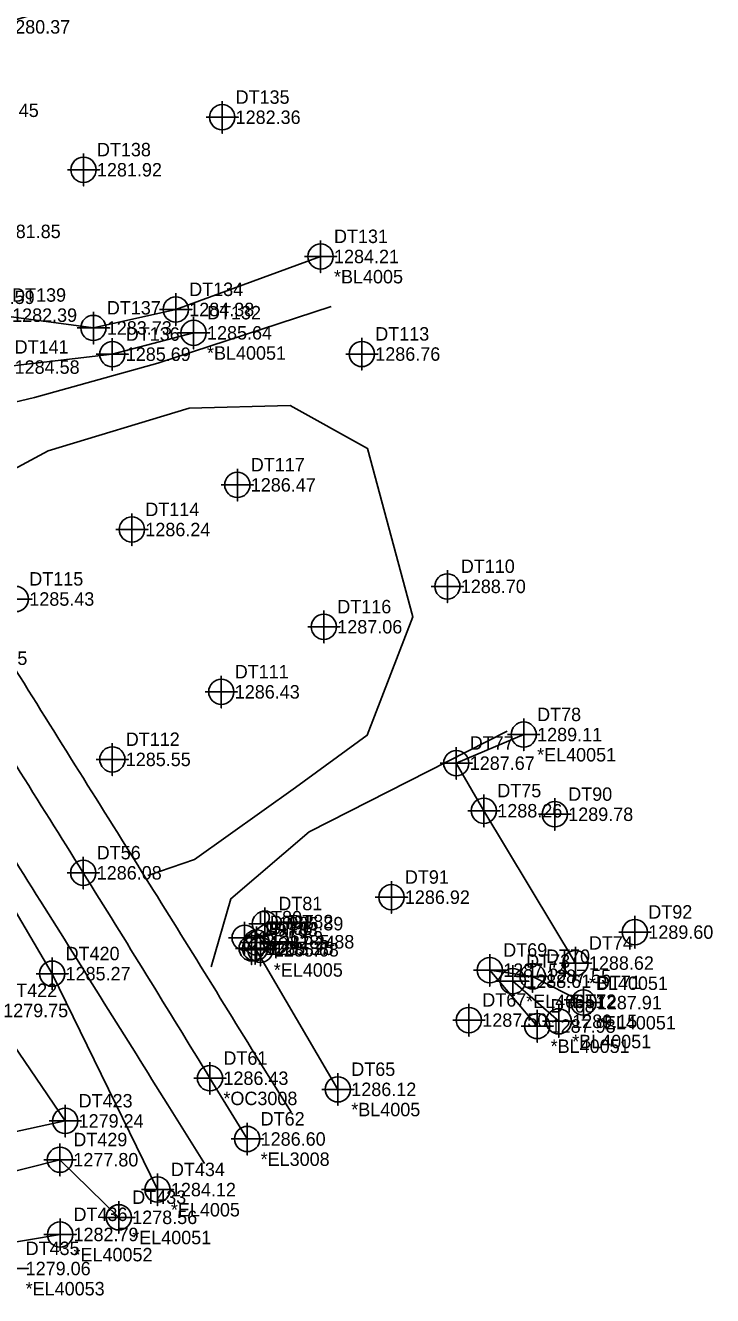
# Model space of a CAD drawing. Extents: x 1394009 to 1394411, y 957864 to 958364.
# Drawn here: x 1394283.7 to 1394411.5, y 957878.6 to 958114.8 of the extents above; entities that cross this region are included whole.
import ezdxf

# ---------------------------------------------------------------- set-up
doc = ezdxf.new("R2010")
doc.units = 0
for name, color, linetype in [('Exist DTM Breakline', 7, 'Continuous'), ('Exist DTM Breakline Cogo Comment', 7, 'Continuous'), ('Exist DTM Breakline Cogo Elevation', 7, 'Continuous'), ('Exist DTM Breakline Cogo Number', 7, 'Continuous'), ('Exist DTM Breakline Cogo Point CELL', 7, 'Continuous'), ('Exist DTM Crownline', 7, 'Continuous'), ('Exist DTM Regular Point Cogo Elevation', 7, 'Continuous'), ('Exist Roads EOP', 7, 'Continuous'), ('Exist Roads Soil', 7, 'Continuous'), ('Exist Structure Minor Culvert Topo', 7, 'Continuous'), ('Exist Structure Minor Culvert Topo Terminator', 7, 'Continuous'), ('Exist Structure Minor Footbridge', 7, 'Continuous'), ('Exist Structure Minor Footbridge Terminator', 7, 'Continuous'), ('PH Exist DTM NCFMP LIDAR Elevation Point', 7, 'Continuous'), ('Raster_Level_0', 7, 'Continuous')]:
    doc.layers.add(name, color=color, linetype=linetype)

msp = doc.modelspace()

# ---------------------------------------------------------------- linework, layer by layer
at = {"layer": 'Exist DTM Breakline'}
for p, q in [((1394382.8635, 957929.5842), (1394374.3045, 957937.0396)), ((1394254.6438, 957883.9212), (1394290.1223, 957889.9518))]:
    msp.add_line(p, q, dxfattribs=at)
for points in [[(1394338.5703, 958071.7873), (1394311.6428, 958061.939), (1394296.3165, 958058.5038), (1394278.7037, 958060.8799), (1394270.8162, 958064.205), (1394260.0757, 958069.6149), (1394248.6938, 958087.5642), (1394243.8244, 958095.3933), (1394260.8199, 958104.7758), (1394277.4189, 958114.4853), (1394301.9851, 958121.8746)], [(1394234.7161, 958087.1493), (1394208.4745, 958071.86), (1394207.051, 958069.7897), (1394210.8783, 958071.9618), (1394213.0858, 958066.3393), (1394211.818, 958067.823), (1394208.5647, 958061.9703), (1394223.9737, 958040.8216), (1394237.157, 958012.3346), (1394253.5006, 957985.8224), (1394267.2603, 957974.749), (1394288.6525, 957938.4432), (1394308.2436, 957898.2998)], [(1394314.9529, 958057.597), (1394299.8393, 958053.6184), (1394279.177, 958051.2301), (1394266.5791, 958043.3997), (1394258.6023, 958048.4386), (1394249.7488, 958062.8318), (1394236.4026, 958078.4617), (1394232.5982, 958084.3218)], [(1394202.6193, 958029.3354), (1394215.0019, 958016.2345), (1394221.6713, 958003.4334), (1394237.1401, 957997.6779), (1394243.3584, 957984.1351), (1394256.2425, 957964.9576), (1394277.0443, 957931.6004), (1394291.0752, 957911.067), (1394259.429, 957904.1903), (1394243.1444, 957902.5266)], [(1394385.9719, 957940.4138), (1394368.9383, 957968.739), (1394363.8098, 957977.5834), (1394376.341, 957982.8965)], [(1394341.7843, 957916.9337), (1394326.395, 957943.1604), (1394325.7531, 957943.1461), (1394324.4454, 957945.1081), (1394328.2194, 957947.7402), (1394330.2585, 957944.3788), (1394327.3729, 957942.881)], [(1394378.8606, 957928.706), (1394370.0349, 957939.0949), (1394378.0113, 957937.9487), (1394387.4448, 957933.0667)], [(1394243.646, 957897.9549), (1394263.7341, 957897.1943), (1394290.0967, 957903.851), (1394301.0447, 957893.1375)]]:
    msp.add_lwpolyline(points, dxfattribs=at)
at = {"layer": 'Exist DTM Breakline Cogo Point CELL'}
for points in [[(1394338.5703, 958074.7873), (1394338.5703, 958068.7873), (1394338.5703, 958071.7873), (1394341.5703, 958071.7873), (1394335.5703, 958071.7873)], [(1394311.6428, 958064.939), (1394311.6428, 958058.939), (1394311.6428, 958061.939), (1394314.6428, 958061.939), (1394308.6428, 958061.939)], [(1394296.3165, 958061.5038), (1394296.3165, 958055.5038), (1394296.3165, 958058.5038), (1394299.3165, 958058.5038), (1394293.3165, 958058.5038)], [(1394314.9529, 958060.597), (1394314.9529, 958054.597), (1394314.9529, 958057.597), (1394317.9529, 958057.597), (1394311.9529, 958057.597)], [(1394299.8393, 958056.6184), (1394299.8393, 958050.6184), (1394299.8393, 958053.6184), (1394302.8393, 958053.6184), (1394296.8393, 958053.6184)], [(1394376.341, 957985.8965), (1394376.341, 957979.8965), (1394376.341, 957982.8965), (1394379.341, 957982.8965), (1394373.341, 957982.8965)], [(1394363.8098, 957980.5834), (1394363.8098, 957974.5834), (1394363.8098, 957977.5834), (1394366.8098, 957977.5834), (1394360.8098, 957977.5834)], [(1394368.9383, 957971.739), (1394368.9383, 957965.739), (1394368.9383, 957968.739), (1394371.9383, 957968.739), (1394365.9383, 957968.739)], [(1394328.2194, 957950.7402), (1394328.2194, 957944.7402), (1394328.2194, 957947.7402), (1394331.2194, 957947.7402), (1394325.2194, 957947.7402)], [(1394324.4454, 957948.1081), (1394324.4454, 957942.1081), (1394324.4454, 957945.1081), (1394327.4454, 957945.1081), (1394321.4454, 957945.1081)], [(1394330.2585, 957947.3788), (1394330.2585, 957941.3788), (1394330.2585, 957944.3788), (1394333.2585, 957944.3788), (1394327.2585, 957944.3788)], [(1394325.7531, 957946.1461), (1394325.7531, 957940.1461), (1394325.7531, 957943.1461), (1394328.7531, 957943.1461), (1394322.7531, 957943.1461)], [(1394326.395, 957946.1604), (1394326.395, 957940.1604), (1394326.395, 957943.1604), (1394329.395, 957943.1604), (1394323.395, 957943.1604)], [(1394327.3729, 957945.881), (1394327.3729, 957939.881), (1394327.3729, 957942.881), (1394330.3729, 957942.881), (1394324.3729, 957942.881)], [(1394385.9719, 957943.4138), (1394385.9719, 957937.4138), (1394385.9719, 957940.4138), (1394388.9719, 957940.4138), (1394382.9719, 957940.4138)], [(1394288.6525, 957941.4432), (1394288.6525, 957935.4432), (1394288.6525, 957938.4432), (1394291.6525, 957938.4432), (1394285.6525, 957938.4432)], [(1394370.0349, 957942.0949), (1394370.0349, 957936.0949), (1394370.0349, 957939.0949), (1394373.0349, 957939.0949), (1394367.0349, 957939.0949)], [(1394374.3045, 957940.0396), (1394374.3045, 957934.0396), (1394374.3045, 957937.0396), (1394377.3045, 957937.0396), (1394371.3045, 957937.0396)], [(1394378.0113, 957940.9487), (1394378.0113, 957934.9487), (1394378.0113, 957937.9487), (1394381.0113, 957937.9487), (1394375.0113, 957937.9487)], [(1394387.4448, 957936.0667), (1394387.4448, 957930.0667), (1394387.4448, 957933.0667), (1394390.4448, 957933.0667), (1394384.4448, 957933.0667)], [(1394378.8606, 957931.706), (1394378.8606, 957925.706), (1394378.8606, 957928.706), (1394381.8606, 957928.706), (1394375.8606, 957928.706)], [(1394382.8635, 957932.5842), (1394382.8635, 957926.5842), (1394382.8635, 957929.5842), (1394385.8635, 957929.5842), (1394379.8635, 957929.5842)], [(1394341.7843, 957919.9337), (1394341.7843, 957913.9337), (1394341.7843, 957916.9337), (1394344.7843, 957916.9337), (1394338.7843, 957916.9337)], [(1394291.0752, 957914.067), (1394291.0752, 957908.067), (1394291.0752, 957911.067), (1394294.0752, 957911.067), (1394288.0752, 957911.067)], [(1394290.0967, 957906.851), (1394290.0967, 957900.851), (1394290.0967, 957903.851), (1394293.0967, 957903.851), (1394287.0967, 957903.851)], [(1394308.2436, 957901.2998), (1394308.2436, 957895.2998), (1394308.2436, 957898.2998), (1394311.2436, 957898.2998), (1394305.2436, 957898.2998)], [(1394301.0447, 957896.1375), (1394301.0447, 957890.1375), (1394301.0447, 957893.1375), (1394304.0447, 957893.1375), (1394298.0447, 957893.1375)], [(1394290.1223, 957892.9518), (1394290.1223, 957886.9518), (1394290.1223, 957889.9518), (1394293.1223, 957889.9518), (1394287.1223, 957889.9518)], [(1394281.2269, 957886.6237), (1394281.2269, 957880.6237), (1394281.2269, 957883.6237), (1394284.2269, 957883.6237), (1394278.2269, 957883.6237)]]:
    msp.add_lwpolyline(points, dxfattribs=at)
for centre in [(1394338.5703, 958071.7873), (1394311.6428, 958061.939), (1394296.3165, 958058.5038), (1394314.9529, 958057.597), (1394299.8393, 958053.6184), (1394376.341, 957982.8965), (1394363.8098, 957977.5834), (1394368.9383, 957968.739), (1394328.2194, 957947.7402), (1394324.4454, 957945.1081), (1394325.7531, 957943.1461), (1394326.395, 957943.1604), (1394327.3729, 957942.881), (1394330.2585, 957944.3788), (1394385.9719, 957940.4138), (1394288.6525, 957938.4432), (1394370.0349, 957939.0949), (1394378.0113, 957937.9487), (1394374.3045, 957937.0396), (1394387.4448, 957933.0667), (1394378.8606, 957928.706), (1394382.8635, 957929.5842), (1394341.7843, 957916.9337), (1394291.0752, 957911.067), (1394290.0967, 957903.851), (1394308.2436, 957898.2998), (1394301.0447, 957893.1375), (1394290.1223, 957889.9518)]:
    msp.add_circle(centre, 2.344, dxfattribs=at)
at = {"layer": 'Exist DTM Crownline'}
msp.add_line((1394318.0033, 957919.003), (1394324.9302, 957907.7064), dxfattribs=at)
msp.add_spline([(1394223.6604, 958072.3799), (1394244.8218, 958037.3795), (1394269.4506, 957997.0996), (1394294.4399, 957957.1952), (1394318.0033, 957919.003)], degree=3, dxfattribs=at)
at = {"layer": 'Exist Roads EOP'}
for p, q in [((1394325.7525, 957924.4929), (1394333.0808, 957912.6872)), ((1394310.1777, 957914.0367), (1394316.9578, 957903.1334))]:
    msp.add_line(p, q, dxfattribs=at)
for points in [[(1394231.4675, 958077.1435), (1394252.9816, 958042.2643), (1394277.1668, 958002.5538), (1394302.3527, 957962.1709), (1394325.7525, 957924.4929)], [(1394215.8384, 958067.9044), (1394237.3577, 958032.1628), (1394261.7049, 957991.7458), (1394286.4849, 957951.9331), (1394310.1777, 957914.0367)]]:
    msp.add_spline(points, degree=3, dxfattribs=at)
at = {"layer": 'Exist Roads Soil'}
for points in [[(1394340.5459, 958062.5087), (1394308.3278, 958051.9593), (1394285.3476, 958045.5699), (1394276.7186, 958043.5458), (1394268.3214, 958038.5621), (1394256.6207, 958038.5618)], [(1394306.4285, 957956.718), (1394315.1027, 957959.6918), (1394333.9061, 957973.0572), (1394347.2179, 957982.7667), (1394355.735, 958004.7936), (1394347.3044, 958036.1133), (1394332.8906, 958044.0577), (1394314.1398, 958043.6186), (1394287.8803, 958035.6785), (1394273.189, 958027.7647), (1394267.8535, 958020.4329)], [(1394318.1935, 957939.6878), (1394321.8524, 957952.3832), (1394336.4295, 957964.8436), (1394373.2483, 957983.5434)]]:
    msp.add_lwpolyline(points, dxfattribs=at)
at = {"layer": 'Exist Structure Minor Culvert Topo Terminator'}
for points in [[(1394294.4399, 957960.1952), (1394294.4399, 957954.1952), (1394294.4399, 957957.1952), (1394297.4399, 957957.1952), (1394291.4399, 957957.1952)], [(1394318.0033, 957922.003), (1394318.0033, 957916.003), (1394318.0033, 957919.003), (1394321.0033, 957919.003), (1394315.0033, 957919.003)], [(1394324.9302, 957910.7064), (1394324.9302, 957904.7064), (1394324.9302, 957907.7064), (1394327.9302, 957907.7064), (1394321.9302, 957907.7064)]]:
    msp.add_lwpolyline(points, dxfattribs=at)
for centre in [(1394294.4399, 957957.1952), (1394318.0033, 957919.003), (1394324.9302, 957907.7064)]:
    msp.add_circle(centre, 2.344, dxfattribs=at)
at = {"layer": 'PH Exist DTM NCFMP LIDAR Elevation Point'}
for points in [[(1394320.2751, 958100.681), (1394320.2751, 958094.681), (1394320.2751, 958097.681), (1394323.2751, 958097.681), (1394317.2751, 958097.681)], [(1394294.4829, 958090.913), (1394294.4829, 958084.913), (1394294.4829, 958087.913), (1394297.4829, 958087.913), (1394291.4829, 958087.913)], [(1394346.2406, 958056.6536), (1394346.2406, 958050.6536), (1394346.2406, 958053.6536), (1394349.2406, 958053.6536), (1394343.2406, 958053.6536)], [(1394323.0901, 958032.3218), (1394323.0901, 958026.3218), (1394323.0901, 958029.3218), (1394326.0901, 958029.3218), (1394320.0901, 958029.3218)], [(1394303.4827, 958024.0203), (1394303.4827, 958018.0203), (1394303.4827, 958021.0203), (1394306.4827, 958021.0203), (1394300.4827, 958021.0203)], [(1394362.1482, 958013.4502), (1394362.1482, 958007.4502), (1394362.1482, 958010.4502), (1394365.1482, 958010.4502), (1394359.1482, 958010.4502)], [(1394281.9056, 958011.1035), (1394281.9056, 958005.1035), (1394281.9056, 958008.1035), (1394284.9056, 958008.1035), (1394278.9056, 958008.1035)], [(1394339.1791, 958005.9422), (1394339.1791, 957999.9422), (1394339.1791, 958002.9422), (1394342.1791, 958002.9422), (1394336.1791, 958002.9422)], [(1394320.1102, 957993.8427), (1394320.1102, 957987.8427), (1394320.1102, 957990.8427), (1394323.1102, 957990.8427), (1394317.1102, 957990.8427)], [(1394299.8422, 957981.2828), (1394299.8422, 957975.2828), (1394299.8422, 957978.2828), (1394302.8422, 957978.2828), (1394296.8422, 957978.2828)], [(1394382.1241, 957971.082), (1394382.1241, 957965.082), (1394382.1241, 957968.082), (1394385.1241, 957968.082), (1394379.1241, 957968.082)], [(1394351.7512, 957955.6649), (1394351.7512, 957949.6649), (1394351.7512, 957952.6649), (1394354.7512, 957952.6649), (1394348.7512, 957952.6649)], [(1394326.6422, 957947.2429), (1394326.6422, 957941.2429), (1394326.6422, 957944.2429), (1394329.6422, 957944.2429), (1394323.6422, 957944.2429)], [(1394397.0204, 957949.1745), (1394397.0204, 957943.1745), (1394397.0204, 957946.1745), (1394400.0204, 957946.1745), (1394394.0204, 957946.1745)], [(1394366.1459, 957932.8104), (1394366.1459, 957926.8104), (1394366.1459, 957929.8104), (1394369.1459, 957929.8104), (1394363.1459, 957929.8104)]]:
    msp.add_lwpolyline(points, dxfattribs=at)
for centre in [(1394320.2751, 958097.681), (1394294.4829, 958087.913), (1394346.2406, 958053.6536), (1394323.0901, 958029.3218), (1394303.4827, 958021.0203), (1394362.1482, 958010.4502), (1394281.9056, 958008.1035), (1394339.1791, 958002.9422), (1394320.1102, 957990.8427), (1394299.8422, 957978.2828), (1394382.1241, 957968.082), (1394351.7512, 957952.6649), (1394397.0204, 957946.1745), (1394326.6422, 957944.2429), (1394366.1459, 957929.8104)]:
    msp.add_circle(centre, 2.344, dxfattribs=at)

# ---------------------------------------------------------------- texts
at = {"layer": 'Exist DTM Breakline Cogo Comment'}
for s, p in [('*BL4005', (1394341.0703, 958066.7873)), ('*BL40051', (1394317.4529, 958052.597)), ('*EL40051', (1394378.841, 957977.8965)), ('*EL4005', (1394329.8729, 957937.881)), ('*BL40051', (1394388.4719, 957935.4138)), ('*EL40051', (1394376.8045, 957932.0396)), ('*EL40051', (1394389.9448, 957928.0667)), ('*BL40051', (1394381.3606, 957923.706)), ('*BL40051', (1394385.3635, 957924.5842)), ('*BL4005', (1394344.2843, 957911.9337)), ('*EL4005', (1394310.7436, 957893.2998)), ('*EL40051', (1394303.5447, 957888.1375)), ('*EL40052', (1394292.6223, 957884.9518)), ('*EL40053', (1394283.7269, 957878.6237))]:
    msp.add_text(s, height=2.5, dxfattribs=at).set_placement(p)
at = {"layer": 'Exist DTM Breakline Cogo Elevation'}
for s, p in [('1280.37', (1394279.9189, 958113.2353)), ('1284.21', (1394341.0703, 958070.5373)), ('1281.59', (1394273.3162, 958062.955)), ('1284.38', (1394314.1428, 958060.689)), ('1282.39', (1394281.2037, 958059.6299)), ('1283.73', (1394298.8165, 958057.2538)), ('1285.64', (1394317.4529, 958056.347)), ('1285.69', (1394302.3393, 958052.3684)), ('1284.58', (1394281.677, 958049.9801)), ('1289.11', (1394378.841, 957981.6465)), ('1287.67', (1394366.3098, 957976.3334)), ('1288.26', (1394371.4383, 957967.489)), ('1285.89', (1394330.7194, 957946.4902)), ('1285.53', (1394326.9454, 957943.8581)), ('1285.88', (1394332.7585, 957943.1288)), ('1285.37', (1394328.2531, 957941.8961)), ('1285.25', (1394328.895, 957941.9104)), ('1285.68', (1394329.8729, 957941.631)), ('1287.54', (1394372.5349, 957937.8449)), ('1288.62', (1394388.4719, 957939.1638)), ('1285.27', (1394291.1525, 957937.1932)), ('1288.61', (1394376.8045, 957935.7896)), ('1287.55', (1394380.5113, 957936.6987)), ('1287.91', (1394389.9448, 957931.8167)), ('1279.75', (1394279.5443, 957930.3504)), ('1289.15', (1394385.3635, 957928.3342)), ('1287.98', (1394381.3606, 957927.456)), ('1286.12', (1394344.2843, 957915.6837)), ('1279.24', (1394293.5752, 957909.817)), ('1277.80', (1394292.5967, 957902.601)), ('1284.12', (1394310.7436, 957897.0498)), ('1278.56', (1394303.5447, 957891.8875)), ('1282.79', (1394292.6223, 957888.7018)), ('1279.06', (1394283.7269, 957882.3737))]:
    msp.add_text(s, height=2.5, dxfattribs=at).set_placement(p)
at = {"layer": 'Exist DTM Breakline Cogo Number'}
for s, p in [('DT131', (1394341.0703, 958074.2873)), ('DT139', (1394281.2037, 958063.3799)), ('DT134', (1394314.1428, 958064.439)), ('DT137', (1394298.8165, 958061.0038)), ('DT132', (1394317.4529, 958060.097)), ('DT136', (1394302.3393, 958056.1184)), ('DT141', (1394281.677, 958053.7301)), ('DT78', (1394378.841, 957985.3965)), ('DT77', (1394366.3098, 957980.0834)), ('DT75', (1394371.4383, 957971.239)), ('DT81', (1394330.7194, 957950.2402)), ('DT80', (1394326.9454, 957947.6081)), ('DT79', (1394328.2531, 957945.6461)), ('DT66', (1394328.895, 957945.6604)), ('DT83', (1394329.8729, 957945.381)), ('DT82', (1394332.7585, 957946.8788)), ('DT74', (1394388.4719, 957942.9138)), ('DT420', (1394291.1525, 957940.9432)), ('DT69', (1394372.5349, 957941.5949)), ('DT70', (1394380.5113, 957940.4487)), ('DT73', (1394376.8045, 957939.5396)), ('DT71', (1394389.9448, 957935.5667)), ('DT422', (1394279.5443, 957934.1004)), ('DT68', (1394381.3606, 957931.206)), ('DT72', (1394385.3635, 957932.0842)), ('DT65', (1394344.2843, 957919.4337)), ('DT423', (1394293.5752, 957913.567)), ('DT429', (1394292.5967, 957906.351)), ('DT434', (1394310.7436, 957900.7998)), ('DT433', (1394303.5447, 957895.6375)), ('DT436', (1394292.6223, 957892.4518)), ('DT435', (1394283.7269, 957886.1237))]:
    msp.add_text(s, height=2.5, dxfattribs=at).set_placement(p)
at = {"layer": 'Exist DTM Regular Point Cogo Elevation'}
for s, p in [('1281.45', (1394274.0694, 958097.7227)), ('1282.36', (1394322.7751, 958096.431)), ('1281.92', (1394296.9829, 958086.663)), ('1281.85', (1394278.1526, 958075.2043)), ('1286.76', (1394348.7406, 958052.4036)), ('1286.47', (1394325.5901, 958028.0718)), ('1286.24', (1394305.9827, 958019.7703)), ('1288.70', (1394364.6482, 958009.2002)), ('1285.43', (1394284.4056, 958006.8535)), ('1287.06', (1394341.6791, 958001.6922)), ('1286.43', (1394322.6102, 957989.5927)), ('1285.55', (1394302.3422, 957977.0328)), ('1289.78', (1394384.6241, 957966.832)), ('1286.92', (1394354.2512, 957951.4149)), ('1289.60', (1394399.5204, 957944.9245)), ('1281.24', (1394329.1422, 957942.9929)), ('1287.50', (1394368.6459, 957928.5604))]:
    msp.add_text(s, height=2.5, dxfattribs=at).set_placement(p)
at = {"layer": 'Exist Structure Minor Culvert Topo'}
for s, p in [('DT56', (1394296.9399, 957959.6952)), ('DT61', (1394320.5033, 957921.503)), ('DT62', (1394327.4302, 957910.2064))]:
    msp.add_text(s, height=2.5, dxfattribs=at).set_placement(p)
at = {"layer": 'Exist Structure Minor Footbridge'}
for s, p in [('*OC3008', (1394320.5033, 957914.003)), ('*EL3008', (1394327.4302, 957902.7064))]:
    msp.add_text(s, height=2.5, dxfattribs=at).set_placement(p)
at = {"layer": 'Exist Structure Minor Footbridge Terminator'}
for s, p in [('1285.85', (1394271.9506, 957995.8496)), ('1286.08', (1394296.9399, 957955.9452)), ('1286.43', (1394320.5033, 957917.753)), ('1286.60', (1394327.4302, 957906.4564))]:
    msp.add_text(s, height=2.5, dxfattribs=at).set_placement(p)
at = {"layer": 'Raster_Level_0'}
for s, p in [('DT135', (1394322.7751, 958100.181)), ('DT138', (1394296.9829, 958090.413)), ('DT113', (1394348.7406, 958056.1536)), ('DT117', (1394325.5901, 958031.8218)), ('DT114', (1394305.9827, 958023.5203)), ('DT110', (1394364.6482, 958012.9502)), ('DT115', (1394284.4056, 958010.6035)), ('DT116', (1394341.6791, 958005.4422)), ('DT111', (1394322.6102, 957993.3427)), ('DT112', (1394302.3422, 957980.7828)), ('DT90', (1394384.6241, 957970.582)), ('DT91', (1394354.2512, 957955.1649)), ('DT92', (1394399.5204, 957948.6745)), ('DT88', (1394329.1422, 957946.7429)), ('DT67', (1394368.6459, 957932.3104))]:
    msp.add_text(s, height=2.5, dxfattribs=at).set_placement(p)

doc.saveas('drawing.dxf')
